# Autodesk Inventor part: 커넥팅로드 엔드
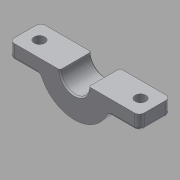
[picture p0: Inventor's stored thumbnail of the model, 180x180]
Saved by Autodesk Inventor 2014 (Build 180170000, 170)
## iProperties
Created: 2016-11
Part Number: 커넥팅로드 엔드
Material: 알루미늄 6061
Document SubType Name: Modeling
Designer: mduedu
Density: 2.71 g/cm^3
Mass: 15.0819 g
Surface Area: 26.6719 cm^2
Volume: 5.56529 cm^3
Appearance: 알루미늄 - 평지
Author: mduedu
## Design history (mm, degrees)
sketch "스케치1" dims "d0" = 30, "d3" = 15
  geometry: L1 (0, 0)-(0, 96); L2 (-5, 90.41)-(-10, 11.18); L3 (5, 90.41)-(10, 11.18); C1 r 6 at (0, 0); C2 r 4 at (0, 96); 3 further points
  constraints: 6 end point, 4 coincident, 2 centre point, 2 symmetric about line, 1 vertical, 6 other
  dimensions: "d1" = 12 diameter of C1; "d2" = 8 diameter of C2; "d4" = 96 distance of L1.start L1.end; "d6" = 10 distance from line of L1 L2.end; "d7" = 5 distance from line of L1 L2.start
extrude "돌출1" new body sketch "스케치1" stored distance "d8" = 13; taper "d9" = 0 deg
extrude "돌출2" join sketch "스케치1" stored distance "d10" = 32; taper "d11" = 0 deg
sketch "스케치2"
  geometry: L1 (5, 90.41)-(10, 11.18) reference; L2 (-5, 90.41)-(-10, 11.18) reference; A1 r 7.5 centre (0, 96) between (5, 90.41) and (-5, 90.41) reference; A2 r 15 centre (0, 0) between (10, 11.18) and (-10, 11.18) reference
extrude "돌출3" join sketch "스케치2" stored distance "d12" = 8; taper "d13" = 0 deg
sketch "스케치3"
  geometry: L1 (-2.732, 78.715)-(-6.171, 24.226); L2 (2.732, 78.715)-(6.171, 24.226); L3 (0, 78.5)-(0, 25); A1 r 17.5 centre (0, 96) between (-2.732, 78.715) and (2.732, 78.715); A2 r 25 centre (0, 0) between (6.171, 24.226) and (-6.171, 24.226); 9 further points; 2 other entities
  constraints: 6 end point, 6 point on circle, 2 centre point, 1 symmetric about line, 1 vertical alignment, 6 other
  dimensions: "d18" = 10 dimension on A1; "d19" = 10 dimension on A2; "d20" = 3 dimension on L1
extrude "돌출4" cut sketch "스케치3" distance "d21" = 2; taper "d22" = 0 deg
fillet "모깎기1" dims "d23" = 2
fillet "모깎기2" dims "d24" = 2
fillet "모깎기3" dims "d25" = 1
chamfer "모따기1" distance "d26" = 0.5; stored, may be unused: second distance "d27" = 2, angle "d28" = 45 deg
sketch "스케치4"
  geometry: L1 (-27, -6)-(-13.748, -6); L2 (27, -6)-(27, 6); L3 (27, 6)-(13.748, 6); L4 (-27, 6)-(-27, -6); L5 (-27, -6)-(27, 6); L6 (27, -6)-(-27, 6); L7 (-13.748, 6)-(-27, 6); L8 (13.748, 6)-(-13.748, 6); L9 (13.748, -6)-(27, -6); L10 (-13.748, -6)-(13.748, -6); A1 r 15 centre (0, 0) between (-13.748, 6) and (13.748, 6) reference; 1 further point
  constraints: 20 end point, 10 parallel, 4 point on circle, 3 horizontal, 3 perpendicular, 2 midpoint
  dimensions: "d29" = 54 distance of L1.start L2.start; "d31" = 12 distance of L2.start L2.end
extrude "돌출5" join sketch "스케치4" stored distance "d32" = 0; taper "d33" = 0 deg
fillet "모깎기4" dims "d34" = 2
fillet "모깎기5" dims "d35" = 1
fillet "모깎기6" dims "d36" = 1
sketch "스케치5"
  geometry: L1 (1, 0)-(1, 9) reference; L2 (-18.5, 20.5)-(-33.5, 20.5) reference; L3 (-33.5, -11.5)-(-18.5, -11.5) reference; L4 (-26, 20.5)-(-26, -11.5); 3 further points
  constraints: 2 end point, 2 midpoint, 1 horizontal alignment, 1 symmetric about line
  dimensions: "d37" = 6 distance from line of point (-5, 4.5) L1
feature "분할1"
sketch "스케치7"
  geometry: 2 further points
  constraints: 2 other
hole "구멍2" sketch "스케치7" at (-47, 4.5), (-5, 4.5) diameter "d45" = 4.5; stored, may be unused: countersink angle "d49" = 90 deg, drill point angle "d51" = 0 deg; dims "d46" = 6, "d47" = 4, "d48" = 2, "d50" = 8
node "솔리드1"
mirror "대칭1"
other parameters: "d16" = 4, "d17" = 4
